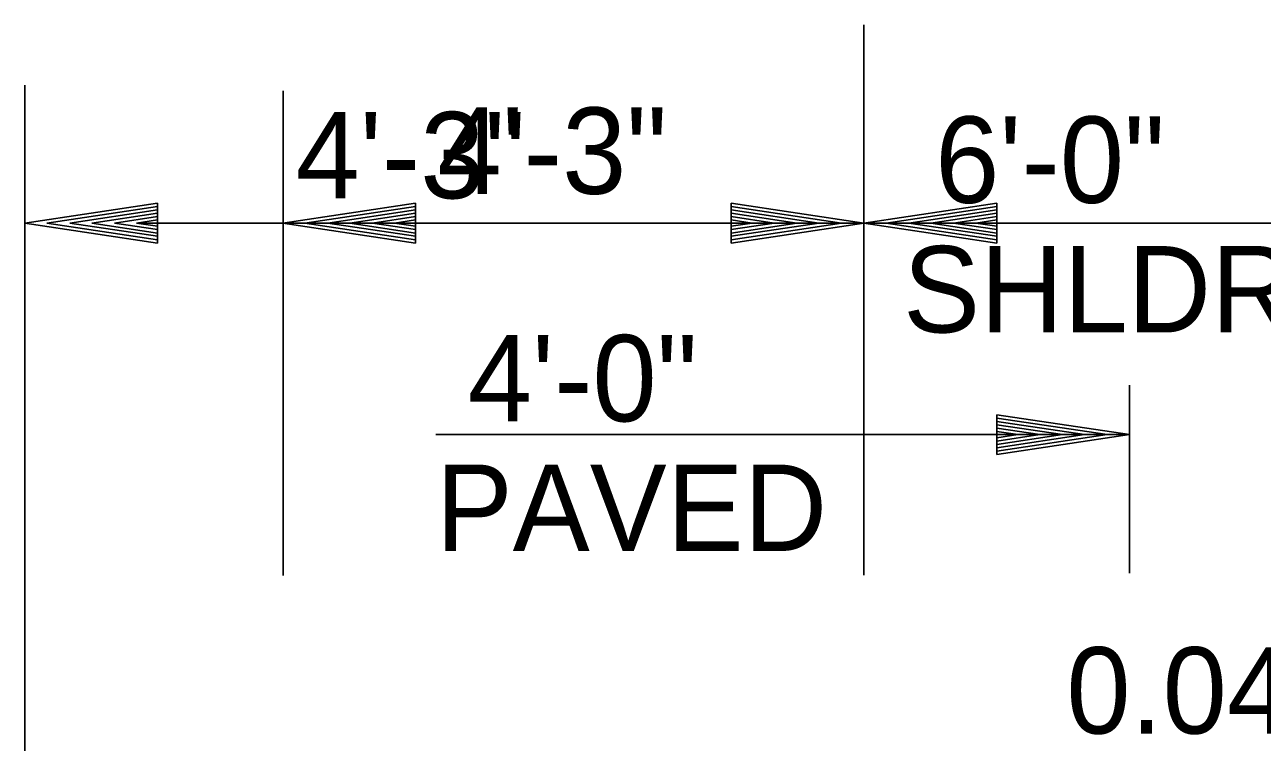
# Model space of a CAD drawing. Extents: x 1373719 to 1374161, y 379835 to 380167.
# Drawn here: x 1373943.4 to 1373952.71, y 380060.44 to 380065.84 of the extents above; entities that cross this region are included whole.
import ezdxf

# ---------------------------------------------------------------- set-up
doc = ezdxf.new("R2010")
doc.units = 0
doc.layers.add('GREEN_TXT', color=7, linetype='Continuous')
doc.layers.add('Text 1', color=7, linetype='Continuous')

msp = doc.modelspace()

# ---------------------------------------------------------------- linework, layer by layer
at = {"layer": 'GREEN_TXT'}
for p, q in [((1373949.7145, 380065.8396), (1373949.7145, 380061.7258)), ((1373943.3975, 380065.3855), (1373943.3975, 380059.2739)), ((1373944.3975, 380064.4972), (1373943.3975, 380064.3472)), ((1373944.3975, 380064.4722), (1373943.5645, 380064.3472)), ((1373944.3975, 380064.1972), (1373944.3975, 380064.4972)), ((1373948.7145, 380064.4972), (1373949.7145, 380064.3472)), ((1373948.7145, 380064.4972), (1373948.7145, 380064.1972)), ((1373948.7145, 380064.4722), (1373949.5475, 380064.3472)), ((1373950.7145, 380064.4972), (1373949.7145, 380064.3472)), ((1373950.7145, 380064.4722), (1373949.8815, 380064.3472)), ((1373950.7145, 380064.1972), (1373950.7145, 380064.4972)), ((1373944.3975, 380064.4467), (1373943.7365, 380064.3472)), ((1373944.3975, 380064.4217), (1373943.903, 380064.3472)), ((1373944.3975, 380064.3962), (1373944.0725, 380064.3472)), ((1373948.7145, 380064.4467), (1373949.3755, 380064.3472)), ((1373948.7145, 380064.4217), (1373949.209, 380064.3472)), ((1373948.7145, 380064.3957), (1373949.0395, 380064.3472)), ((1373950.7145, 380064.4467), (1373950.0535, 380064.3472)), ((1373950.7145, 380064.4217), (1373950.22, 380064.3472)), ((1373950.7145, 380064.3962), (1373950.3895, 380064.3472)), ((1373944.3975, 380064.1972), (1373943.3975, 380064.3472)), ((1373944.3975, 380064.2222), (1373943.5645, 380064.3472)), ((1373944.3975, 380064.2477), (1373943.7365, 380064.3472)), ((1373944.3975, 380064.2727), (1373943.903, 380064.3472)), ((1373944.3975, 380064.2987), (1373944.0725, 380064.3472)), ((1373944.3975, 380064.3707), (1373944.2395, 380064.3472)), ((1373944.3975, 380064.3237), (1373944.2395, 380064.3472)), ((1373949.7145, 380064.3472), (1373944.2671, 380064.3472)), ((1373948.7145, 380064.3707), (1373948.8725, 380064.3472)), ((1373948.7145, 380064.1972), (1373949.7145, 380064.3472)), ((1373948.7145, 380064.2982), (1373949.0395, 380064.3472)), ((1373948.7145, 380064.2477), (1373949.3755, 380064.3472)), ((1373948.7145, 380064.2222), (1373949.5475, 380064.3472)), ((1373948.7145, 380064.2727), (1373949.209, 380064.3472)), ((1373948.7145, 380064.3237), (1373948.8725, 380064.3472)), ((1373950.7145, 380064.1972), (1373949.7145, 380064.3472)), ((1373953.7145, 380064.3472), (1373949.7145, 380064.3472)), ((1373950.7145, 380064.2222), (1373949.8815, 380064.3472)), ((1373950.7145, 380064.2477), (1373950.0535, 380064.3472)), ((1373950.7145, 380064.2727), (1373950.22, 380064.3472)), ((1373950.7145, 380064.2987), (1373950.3895, 380064.3472)), ((1373950.7145, 380064.3707), (1373950.5565, 380064.3472)), ((1373950.7145, 380064.3237), (1373950.5565, 380064.3472))]:
    msp.add_line(p, q, dxfattribs=at)
at = {"layer": 'Text 1'}
for p, q in [((1373945.3422, 380061.695), (1373945.3422, 380065.343)), ((1373946.3399, 380064.4972), (1373945.3399, 380064.3472)), ((1373946.3399, 380064.4722), (1373945.5069, 380064.3472)), ((1373946.3399, 380064.1972), (1373946.3399, 380064.4972)), ((1373948.7145, 380064.4972), (1373949.7145, 380064.3472)), ((1373948.7145, 380064.4972), (1373948.7145, 380064.1972)), ((1373948.7145, 380064.4722), (1373949.5475, 380064.3472)), ((1373946.3399, 380064.4467), (1373945.6789, 380064.3472)), ((1373946.3399, 380064.4217), (1373945.8454, 380064.3472)), ((1373946.3399, 380064.3962), (1373946.0149, 380064.3472)), ((1373948.7145, 380064.4467), (1373949.3755, 380064.3472)), ((1373948.7145, 380064.4217), (1373949.209, 380064.3472)), ((1373948.7145, 380064.3957), (1373949.0395, 380064.3472)), ((1373949.5895, 380064.3472), (1373945.3395, 380064.3472)), ((1373946.3399, 380064.1972), (1373945.3399, 380064.3472)), ((1373946.3399, 380064.2222), (1373945.5069, 380064.3472)), ((1373946.3399, 380064.2477), (1373945.6789, 380064.3472)), ((1373946.3399, 380064.2727), (1373945.8454, 380064.3472)), ((1373946.3399, 380064.2987), (1373946.0149, 380064.3472)), ((1373946.3399, 380064.3707), (1373946.1819, 380064.3472)), ((1373946.3399, 380064.3237), (1373946.1819, 380064.3472)), ((1373948.7145, 380064.3707), (1373948.8725, 380064.3472)), ((1373948.7145, 380064.1972), (1373949.7145, 380064.3472)), ((1373948.7145, 380064.2982), (1373949.0395, 380064.3472)), ((1373948.7145, 380064.2477), (1373949.3755, 380064.3472)), ((1373948.7145, 380064.2222), (1373949.5475, 380064.3472)), ((1373948.7145, 380064.2727), (1373949.209, 380064.3472)), ((1373948.7145, 380064.3237), (1373948.8725, 380064.3472)), ((1373951.7145, 380063.1277), (1373951.7145, 380061.7123)), ((1373950.7145, 380062.9056), (1373951.7145, 380062.7556)), ((1373950.7145, 380062.9056), (1373950.7145, 380062.6056)), ((1373950.7145, 380062.8806), (1373951.5475, 380062.7556)), ((1373950.7145, 380062.8551), (1373951.3755, 380062.7556)), ((1373950.7145, 380062.8301), (1373951.209, 380062.7556)), ((1373950.7145, 380062.8041), (1373951.0395, 380062.7556)), ((1373951.7145, 380062.7556), (1373946.4913, 380062.7556)), ((1373950.7145, 380062.7791), (1373950.8725, 380062.7556)), ((1373950.7145, 380062.6056), (1373951.7145, 380062.7556)), ((1373950.7145, 380062.7066), (1373951.0395, 380062.7556)), ((1373950.7145, 380062.6561), (1373951.3755, 380062.7556)), ((1373950.7145, 380062.6306), (1373951.5475, 380062.7556)), ((1373950.7145, 380062.6811), (1373951.209, 380062.7556)), ((1373950.7145, 380062.7321), (1373950.8725, 380062.7556)), ((1373949.7145, 380062.6056), (1373949.7145, 380061.6992))]:
    msp.add_line(p, q, dxfattribs=at)

# ---------------------------------------------------------------- texts
at = {"layer": 'GREEN_TXT'}
for s, p in [('4\'-3"', (1373945.4363, 380064.5336)), (' 6\'-0"', (1373950.0098, 380064.4995)), ('SHLDR.', (1373950.0098, 380063.5245))]:
    msp.add_text(s, height=0.65, dxfattribs=at).set_placement(p)
msp.add_text("0.04'/'", height=0.65, rotation=359.98, dxfattribs=at).set_placement((1373951.239, 380060.5063))
at = {"layer": 'Text 1'}
for s, p in [('4\'-3"', (1373946.5042, 380064.5671)), (' 4\'-0" ', (1373946.4913, 380062.8554)), ('PAVED', (1373946.4913, 380061.8804))]:
    msp.add_text(s, height=0.65, dxfattribs=at).set_placement(p)

doc.saveas('drawing.dxf')
